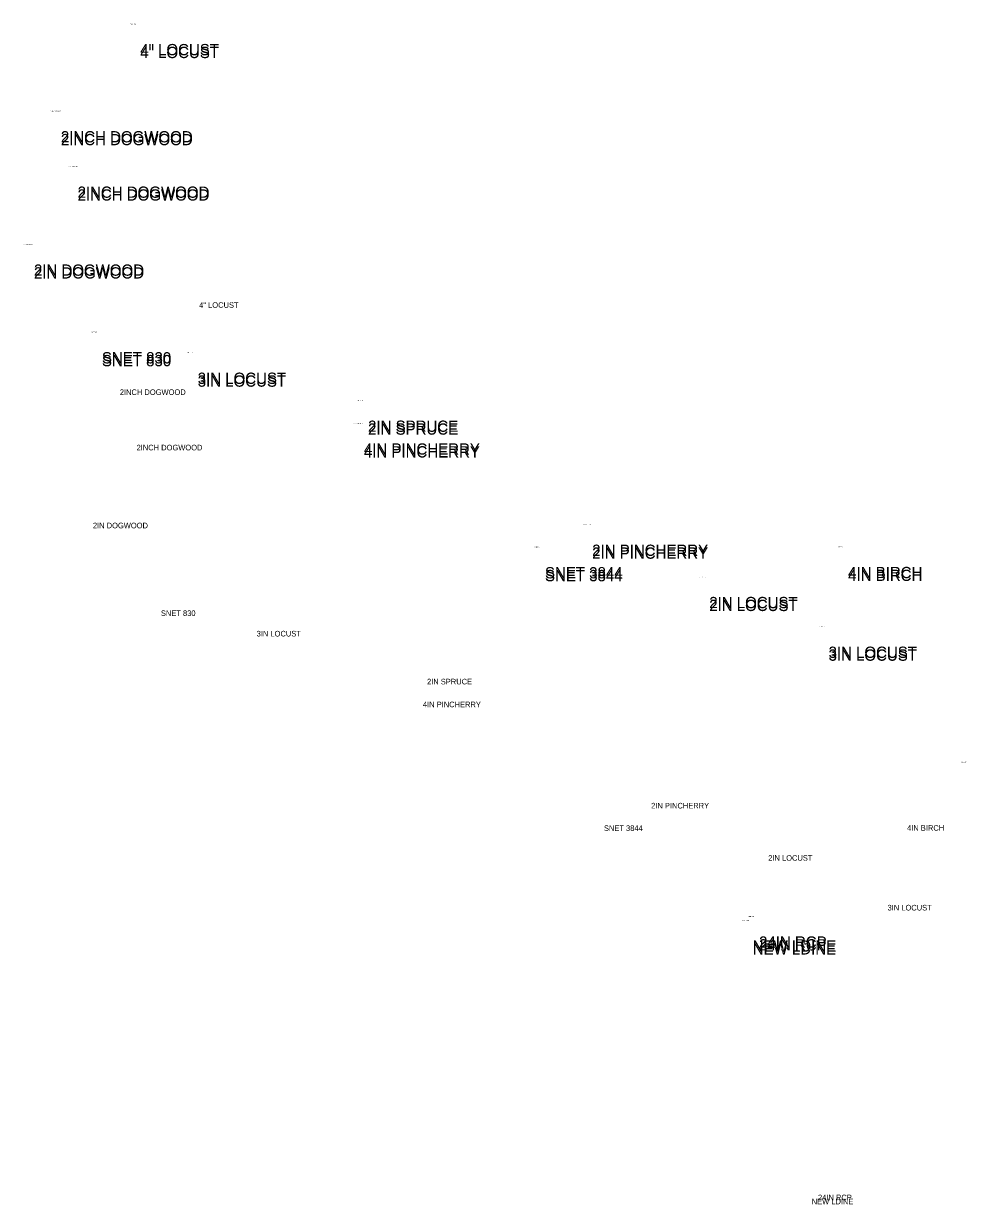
# Model space of a CAD drawing. Extents: x 5447 to 709667, y 4528 to 375472.
# Drawn here: x 708153.2 to 708421.9, y 374033.7 to 374370.2 of the extents above; entities that cross this region are included whole.
import ezdxf

# ---------------------------------------------------------------- set-up
doc = ezdxf.new("R2010")
doc.units = 0
doc.layers.add('SV_SURVEY_NOTES', color=7, linetype='Continuous')

msp = doc.modelspace()

# ---------------------------------------------------------------- texts
at = {"layer": 'SV_SURVEY_NOTES'}
for s, height, p in [('4" LOCUST', 0.25, (708183.45, 374369.97)), ('4" LOCUST', 3.2, (708186.41, 374361.22)), ('4" LOCUST', 3.2, (708186.41, 374361.22)), ('4" LOCUST', 3.2, (708186.41, 374361.22)), ('4" LOCUST', 3.2, (708186.42, 374361.2)), ('4" LOCUST', 3.2, (708186.42, 374361.2)), ('4" LOCUST', 3.2, (708186.42, 374361.2)), ('4" LOCUST', 3.2, (708186.42, 374361.2)), ('4" LOCUST', 3.2, (708186.42, 374361.2)), ('4" LOCUST', 3.2, (708186.41, 374360.42)), ('4" LOCUST', 3.2, (708186.42, 374360.4)), ('4" LOCUST', 3.2, (708186.43, 374360.39)), ('2INCH DOGWOOD', 0.25, (708160.82, 374345.13)), ('2INCH DOGWOOD', 3.2, (708163.78, 374336.38)), ('2INCH DOGWOOD', 3.2, (708163.78, 374336.38)), ('2INCH DOGWOOD', 3.2, (708163.78, 374336.38)), ('2INCH DOGWOOD', 3.2, (708163.78, 374335.58)), ('2INCH DOGWOOD', 3.2, (708163.8, 374336.37)), ('2INCH DOGWOOD', 3.2, (708163.8, 374336.37)), ('2INCH DOGWOOD', 3.2, (708163.8, 374336.37)), ('2INCH DOGWOOD', 3.2, (708163.8, 374336.37)), ('2INCH DOGWOOD', 3.2, (708163.8, 374336.37)), ('2INCH DOGWOOD', 3.2, (708163.8, 374335.57)), ('2INCH DOGWOOD', 3.2, (708163.8, 374335.56)), ('2INCH DOGWOOD', 0.25, (708165.6, 374329.34)), ('2INCH DOGWOOD', 3.2, (708168.55, 374320.59)), ('2INCH DOGWOOD', 3.2, (708168.55, 374320.59)), ('2INCH DOGWOOD', 3.2, (708168.55, 374320.59)), ('2INCH DOGWOOD', 3.2, (708168.55, 374319.79)), ('2INCH DOGWOOD', 3.2, (708168.57, 374319.77)), ('2INCH DOGWOOD', 3.2, (708168.57, 374320.58)), ('2INCH DOGWOOD', 3.2, (708168.57, 374320.58)), ('2INCH DOGWOOD', 3.2, (708168.57, 374320.58)), ('2INCH DOGWOOD', 3.2, (708168.57, 374320.58)), ('2INCH DOGWOOD', 3.2, (708168.57, 374320.58)), ('2INCH DOGWOOD', 3.2, (708168.57, 374319.78)), ('2IN DOGWOOD', 0.25, (708153.15, 374307.13)), ('2IN DOGWOOD', 3.2, (708156.11, 374298.38)), ('2IN DOGWOOD', 3.2, (708156.11, 374298.38)), ('2IN DOGWOOD', 3.2, (708156.11, 374298.38)), ('2IN DOGWOOD', 3.2, (708156.11, 374297.58)), ('2IN DOGWOOD', 3.2, (708156.12, 374297.56)), ('2IN DOGWOOD', 3.2, (708156.12, 374298.36)), ('2IN DOGWOOD', 3.2, (708156.12, 374298.36)), ('2IN DOGWOOD', 3.2, (708156.12, 374298.36)), ('2IN DOGWOOD', 3.2, (708156.12, 374298.36)), ('2IN DOGWOOD', 3.2, (708156.12, 374298.36)), ('2IN DOGWOOD', 3.2, (708156.12, 374297.56)), ('4" LOCUST', 1.6, (708203.22, 374289.2)), ('SNET 830', 0.25, (708172.52, 374282.13)), ('SNET 830', 3.2, (708175.48, 374273.38)), ('SNET 830', 3.2, (708175.48, 374273.38)), ('SNET 830', 3.2, (708175.48, 374273.38)), ('SNET 830', 3.2, (708175.48, 374272.58)), ('SNET 830', 3.2, (708175.5, 374273.37)), ('SNET 830', 3.2, (708175.5, 374273.37)), ('SNET 830', 3.2, (708175.5, 374273.37)), ('SNET 830', 3.2, (708175.5, 374273.37)), ('SNET 830', 3.2, (708175.5, 374273.37)), ('SNET 830', 3.2, (708175.5, 374272.57)), ('SNET 830', 3.2, (708175.49, 374272.56)), ('3IN LOCUST', 0.25, (708199.83, 374276.3)), ('3IN LOCUST', 3.2, (708202.79, 374267.55)), ('3IN LOCUST', 3.2, (708202.79, 374267.55)), ('3IN LOCUST', 3.2, (708202.79, 374267.55)), ('3IN LOCUST', 3.2, (708202.8, 374267.53)), ('3IN LOCUST', 3.2, (708202.8, 374267.53)), ('3IN LOCUST', 3.2, (708202.8, 374267.53)), ('3IN LOCUST', 3.2, (708202.8, 374267.53)), ('3IN LOCUST', 3.2, (708202.8, 374267.53)), ('3IN LOCUST', 3.2, (708202.79, 374266.75)), ('3IN LOCUST', 3.2, (708202.8, 374266.72)), ('3IN LOCUST', 3.2, (708202.8, 374266.73)), ('2INCH DOGWOOD', 1.6, (708180.59, 374264.37)), ('2IN SPRUCE', 0.25, (708248.39, 374262.64)), ('2IN SPRUCE', 3.2, (708251.35, 374253.88)), ('2IN SPRUCE', 3.2, (708251.35, 374253.88)), ('2IN SPRUCE', 3.2, (708251.35, 374253.88)), ('2IN SPRUCE', 3.2, (708251.37, 374253.87)), ('2IN SPRUCE', 3.2, (708251.37, 374253.87)), ('2IN SPRUCE', 3.2, (708251.37, 374253.87)), ('2IN SPRUCE', 3.2, (708251.37, 374253.87)), ('2IN SPRUCE', 3.2, (708251.37, 374253.87)), ('4IN PINCHERRY', 0.25, (708247.21, 374256.14)), ('2IN SPRUCE', 3.2, (708251.35, 374253.08)), ('2IN SPRUCE', 3.2, (708251.36, 374253.05)), ('2IN SPRUCE', 3.2, (708251.37, 374253.07)), ('2INCH DOGWOOD', 1.6, (708185.37, 374248.58)), ('4IN PINCHERRY', 3.2, (708250.17, 374247.38)), ('4IN PINCHERRY', 3.2, (708250.17, 374247.38)), ('4IN PINCHERRY', 3.2, (708250.17, 374247.38)), ('4IN PINCHERRY', 3.2, (708250.18, 374247.37)), ('4IN PINCHERRY', 3.2, (708250.18, 374247.37)), ('4IN PINCHERRY', 3.2, (708250.18, 374247.37)), ('4IN PINCHERRY', 3.2, (708250.18, 374247.37)), ('4IN PINCHERRY', 3.2, (708250.18, 374247.37)), ('4IN PINCHERRY', 3.2, (708250.17, 374246.58)), ('4IN PINCHERRY', 3.2, (708250.18, 374246.57)), ('4IN PINCHERRY', 3.2, (708250.18, 374246.55)), ('2IN DOGWOOD', 1.6, (708172.92, 374226.36)), ('2IN PINCHERRY', 0.25, (708312.27, 374227.27)), ('SNET 3844', 0.25, (708298.83, 374220.86)), ('2IN PINCHERRY', 3.2, (708315.23, 374218.52)), ('2IN PINCHERRY', 3.2, (708315.23, 374218.52)), ('2IN PINCHERRY', 3.2, (708315.23, 374218.52)), ('2IN PINCHERRY', 3.2, (708315.23, 374217.72)), ('2IN PINCHERRY', 3.2, (708315.24, 374217.68)), ('2IN PINCHERRY', 3.2, (708315.25, 374218.51)), ('2IN PINCHERRY', 3.2, (708315.25, 374218.51)), ('2IN PINCHERRY', 3.2, (708315.25, 374218.51)), ('2IN PINCHERRY', 3.2, (708315.25, 374218.51)), ('2IN PINCHERRY', 3.2, (708315.25, 374218.51)), ('2IN PINCHERRY', 3.2, (708315.25, 374217.71)), ('4IN BIRCH', 0.25, (708385.24, 374220.94)), ('SNET 3844', 3.2, (708301.78, 374212.11)), ('SNET 3844', 3.2, (708301.78, 374212.11)), ('SNET 3844', 3.2, (708301.78, 374212.11)), ('SNET 3844', 3.2, (708301.78, 374211.31)), ('SNET 3844', 3.2, (708301.79, 374211.27)), ('SNET 3844', 3.2, (708301.8, 374212.1)), ('SNET 3844', 3.2, (708301.8, 374212.1)), ('SNET 3844', 3.2, (708301.8, 374212.1)), ('SNET 3844', 3.2, (708301.8, 374212.1)), ('SNET 3844', 3.2, (708301.8, 374212.1)), ('SNET 3844', 3.2, (708301.8, 374211.3)), ('4IN BIRCH', 3.2, (708388.2, 374212.18)), ('4IN BIRCH', 3.2, (708388.2, 374212.18)), ('4IN BIRCH', 3.2, (708388.2, 374212.18)), ('4IN BIRCH', 3.2, (708388.2, 374211.38)), ('4IN BIRCH', 3.2, (708388.22, 374212.16)), ('4IN BIRCH', 3.2, (708388.22, 374212.16)), ('4IN BIRCH', 3.2, (708388.22, 374212.16)), ('4IN BIRCH', 3.2, (708388.22, 374212.16)), ('4IN BIRCH', 3.2, (708388.22, 374212.16)), ('4IN BIRCH', 3.2, (708388.22, 374211.36)), ('4IN BIRCH', 3.2, (708388.22, 374211.36)), ('2IN LOCUST', 0.25, (708345.66, 374212.37)), ('2IN LOCUST', 3.2, (708348.61, 374203.62)), ('2IN LOCUST', 3.2, (708348.61, 374203.62)), ('2IN LOCUST', 3.2, (708348.61, 374203.62)), ('2IN LOCUST', 3.2, (708348.63, 374203.61)), ('2IN LOCUST', 3.2, (708348.63, 374203.61)), ('2IN LOCUST', 3.2, (708348.63, 374203.61)), ('2IN LOCUST', 3.2, (708348.63, 374203.61)), ('2IN LOCUST', 3.2, (708348.63, 374203.61)), ('SNET 830', 1.6, (708192.3, 374201.37)), ('2IN LOCUST', 3.2, (708348.61, 374202.82)), ('2IN LOCUST', 3.2, (708348.62, 374202.78)), ('2IN LOCUST', 3.2, (708348.63, 374202.81)), ('3IN LOCUST', 1.6, (708219.6, 374195.54)), ('3IN LOCUST', 0.25, (708379.67, 374198.21)), ('3IN LOCUST', 3.2, (708382.62, 374189.45)), ('3IN LOCUST', 3.2, (708382.62, 374189.45)), ('3IN LOCUST', 3.2, (708382.62, 374189.45)), ('3IN LOCUST', 3.2, (708382.62, 374188.65)), ('3IN LOCUST', 3.2, (708382.63, 374188.61)), ('3IN LOCUST', 3.2, (708382.64, 374189.44)), ('3IN LOCUST', 3.2, (708382.64, 374189.44)), ('3IN LOCUST', 3.2, (708382.64, 374189.44)), ('3IN LOCUST', 3.2, (708382.64, 374189.44)), ('3IN LOCUST', 3.2, (708382.64, 374189.44)), ('3IN LOCUST', 3.2, (708382.64, 374188.64)), ('2IN SPRUCE', 1.6, (708268.17, 374181.87)), ('4IN PINCHERRY', 1.6, (708266.99, 374175.37)), ('SNET 831', 0.25, (708420.39, 374159.59)), ('2IN PINCHERRY', 1.6, (708332.05, 374146.51)), ('SNET 3844', 1.6, (708318.59, 374140.1)), ('4IN BIRCH', 1.6, (708405.01, 374140.17)), ('2IN LOCUST', 1.6, (708365.43, 374131.61)), ('3IN LOCUST', 1.6, (708399.44, 374117.44)), ('24IN RCP', 0.25, (708359.85, 374115.61)), ('NEW LDINE', 0.25, (708358.05, 374114.44)), ('NEW LDINE', 3.2, (708361.01, 374105.69)), ('NEW LDINE', 3.2, (708361.01, 374105.69)), ('NEW LDINE', 3.2, (708361.01, 374105.69)), ('NEW LDINE', 3.2, (708361.03, 374105.67)), ('NEW LDINE', 3.2, (708361.03, 374105.67)), ('NEW LDINE', 3.2, (708361.03, 374105.67)), ('NEW LDINE', 3.2, (708361.03, 374105.67)), ('NEW LDINE', 3.2, (708361.03, 374105.67)), ('24IN RCP', 3.2, (708362.81, 374106.86)), ('24IN RCP', 3.2, (708362.81, 374106.86)), ('24IN RCP', 3.2, (708362.81, 374106.86)), ('24IN RCP', 3.2, (708362.81, 374106.06)), ('24IN RCP', 3.2, (708362.83, 374106.84)), ('24IN RCP', 3.2, (708362.83, 374106.84)), ('24IN RCP', 3.2, (708362.83, 374106.84)), ('24IN RCP', 3.2, (708362.83, 374106.84)), ('24IN RCP', 3.2, (708362.83, 374106.84)), ('24IN RCP', 3.2, (708362.83, 374106.04)), ('24IN RCP', 3.2, (708362.83, 374106.04)), ('NEW LDINE', 3.2, (708361.01, 374104.89)), ('NEW LDINE', 3.2, (708361.03, 374104.87)), ('NEW LDINE', 3.2, (708361.03, 374104.87)), ('NEW LDINE', 1.6, (708377.83, 374033.67)), ('24IN RCP', 1.6, (708379.62, 374034.84))]:
    msp.add_text(s, height=height, dxfattribs=at).set_placement(p)

doc.saveas('drawing.dxf')
